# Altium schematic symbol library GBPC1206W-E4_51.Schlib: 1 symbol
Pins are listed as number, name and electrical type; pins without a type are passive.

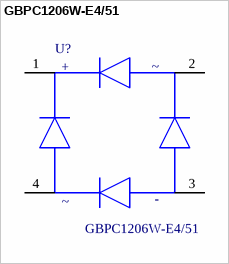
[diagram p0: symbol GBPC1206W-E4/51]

## GBPC1206W-E4/51
designator U?
DISCRETE, DIODE 1PH 12A 600V, GBPC-W; Manufacturer: VISHAY SEMICONDUCTOR; CompType: RECTIFIER; SymbolCreator: x0199378
pins: 1, 2, 3, 4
